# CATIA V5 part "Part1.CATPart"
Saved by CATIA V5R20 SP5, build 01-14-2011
Part number: Part1
Bounding box of the stored display mesh (mm): x -40 to 40, y -20 to 20, z 0 to 80
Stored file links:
  C:\!Work\00_Catia\Makro+Unfold\sestava\Nová složka\Part1.CATPart
  C:\!Work\00_Catia\Makro+Unfold\sestava\Nová složka\Part2.CATPart
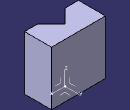
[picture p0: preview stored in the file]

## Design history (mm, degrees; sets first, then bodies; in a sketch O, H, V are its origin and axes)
AxisSystem1: origin (0, 0, 0), X (1, 0, 0), Y (0, 1, 0), Z (0, 0, 1)
Body1 (main body)
  Sketch1 on xy-plane, origin (0, 0, 0), H (1, 0, 0), V (0, 1, 0)
    line L1 (40, 20) -> (-40, 20)
    line L2 (-40, 20) -> (-40, -20)
    line L3 (-40, -20) -> (-20, -20)
    line L4 (-20, -20) -> (0, 0)
    point P5 (0, 0)
    line L5 (0, 0) -> (20, -20)
    point P6 (20, -20)
    line L6 (20, -20) -> (40, -20)
    line L7 (40, -20) -> (40, 20)
    reference projected line E1 through (0, 0) direction (0, 1) from edge [YZ plane of AxisSystem1 | XY plane of AxisSystem1]
    reference projected line E2 through (0, 0) direction (0, 1) from edge [YZ plane of AxisSystem1 | XY plane of AxisSystem1]
    reference projected line E3 through (0, 0) direction (1, 0) from edge [XY plane of AxisSystem1 | ZX plane of AxisSystem1]
    distance E3 L1 = 20
    distance L1 L3 = 40
    angle L4 L5 = 90
    distance L2 L7 = 80
    horizontal: L1 H, L3 H, L6 H
    vertical: L2 V, L7 V
    coincidence: P5 V, P5 H, P6 L3
    symmetry: L7 L2 E1, L4 L5 E2
  Pad1: profile Sketch1, direction (0, 0, 1), length 80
